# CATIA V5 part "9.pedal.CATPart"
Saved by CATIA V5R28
Part number: 9.pedal
Bounding box of the stored display mesh (mm): x -60 to 51, y -42 to 42, z -15 to 15
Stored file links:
  D:\Catia Cycle design\9.pedal.CATPart
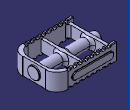
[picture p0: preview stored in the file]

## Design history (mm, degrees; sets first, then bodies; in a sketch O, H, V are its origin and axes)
Set1
  Sketch1 on xy-plane, origin (0, 0, 0), H (1, 0, 0), V (0, 1, 0)
    line L1 (50, 40) -> (50, -40)
    line L2 (50, -40) -> (-50, -40)
    line L3 (-50, -40) -> (-50, 40)
    line L4 (-50, 40) -> (50, 40)
    point P2 (50, -40)
    distance P2 L4 = 80
    length L4 = 100
    vertical: L1 V, L3 V
    horizontal: L2 H, L4 H
    equidistance: L1 L3 O, L2 L4 O
Body1 (main body)
  Pad1: profile Sketch1, direction (0, 0, 1), length 15, mirrored extent
  Sketch2 on end face of Pad1, origin (0, 0, 15), H (1, 0, 0), V (0, 1, 0)
    point P1 (-45, 35)
    line L1 (-45, 35) -> (-2.35, 35)
    line L2 (-2.35, 35) -> (-2.35, 12)
    line L3 (-2.35, 12) -> (-45, 12)
    line L4 (-45, 12) -> (-45, 35)
    point P2 (-2.35, 35)
    point P3 (-2.35, 12)
    point P4 (-45, 12)
    reference projected line E1 (50, 40) -> (-50, 40) from edge [face of Pad1 from Sketch1.L4 | end face of Pad1]
    reference projected line E2 (-50, 40) -> (-50, -40) from edge [face of Pad1 from Sketch1.L3 | end face of Pad1]
    point P5 (2.35, 12)
    point P6 (2.35, 35)
    line L5 (2.35, 35) -> (2.35, 12)
    point P7 (45, 12)
    line L6 (2.35, 12) -> (45, 12)
    point P8 (45, 35)
    line L7 (45, 12) -> (45, 35)
    line L8 (45, 35) -> (2.35, 35)
    point P9 (-45, -35)
    point P10 (-2.35, -35)
    point P11 (-2.35, -12)
    point P12 (-45, -12)
    point P13 (2.35, -12)
    point P14 (2.35, -35)
    point P15 (45, -12)
    point P16 (45, -35)
    line L9 (-45, -35) -> (-2.35, -35)
    line L10 (-2.35, -35) -> (-2.35, -12)
    line L11 (-2.35, -12) -> (-45, -12)
    line L12 (-45, -12) -> (-45, -35)
    line L13 (2.35, -35) -> (2.35, -12)
    line L14 (2.35, -12) -> (45, -12)
    line L15 (45, -12) -> (45, -35)
    line L16 (45, -35) -> (2.35, -35)
    length L1 = 42.65
    length L4 = 23
    distance L1 E1 = 5
    distance L4 E2 = 5
    horizontal: L1 H, L3 H
    vertical: L2 V, L4 V
    symmetry: P3 P5 V, P2 P6 V, L2 L5 V, P4 P7 V, L3 L6 V, P1 P8 V, L4 L7 V, L1 L8 V, P1 P9 H, P2 P10 H, P3 P11 H, P4 P12 H, P5 P13 H, P6 P14 H, P7 P15 H, P8 P16 H, L1 L9 H, L2 L10 H, L3 L11 H, L4 L12 H, L5 L13 H, L6 L14 H, L7 L15 H, L8 L16 H
  Pocket1: profile Sketch2, direction (0, 0, -1), through (limit type 6)
  Sketch3 on face of Pad1 from Sketch1.L1, origin (50, 0, 0), H (0, 1, 0), V (0, 0, 1)
    circle A1 centre (0, 0) radius 7.5
    radius A1 = 7.5
  Pocket2: profile Sketch3, direction (-1, 0, 0), through (limit type 6)
  Sketch4 on face of Pocket1 from Sketch2.L12, origin (-45, 0, 0), H (0, 1, 0), V (0, 0, 1)
    circle A1 centre (0, 0) radius 8.5
    circle A2 centre (0, 0) radius 20
    radius A1 = 8.5
    radius A2 = 20
  Pocket3: profile Sketch4, direction (1, 0, 0), length 42.65
  Sketch5 on face of Pocket1 from Sketch2.L13, origin (2.35, 0, 0), H (0, 1, 0), V (0, 0, 1)
    projected circle E1 centre (0, 0) radius 8.5 from Sketch4.A1
    projected circle E2 centre (0, 0) radius 20 from Sketch4.A2
  Pocket4: profile Sketch5, direction (1, 0, 0), length 42.65
  Fillet1: radius 20, on edge [face of Pocket1 from Sketch2.L8 | face of Pocket4]; edge [face of Pocket4 | face of Pocket1 from Sketch2.L16]; edge [face of Pad1 from Sketch1.L1 | face of Pad1 from Sketch1.L2]; edge [face of Pad1 from Sketch1.L4 | face of Pad1 from Sketch1.L1]
  Sketch6 on end face of Pad1, origin (0, 0, 15), H (1, 0, 0), V (0, 1, 0)
    line L1 (-50, 35) -> (-45, 35)
    line L2 (-45, 35) -> (-45, -35)
    line L3 (-45, -35) -> (-50, -35)
    line L4 (-50, -35) -> (-50, 35)
    reference projected line E1 (-2.35, 35) -> (-45, 35) from edge [end face of Pad1 | face of Pocket1 from Sketch2.L1]
    reference projected line E2 (-45, 35) -> (-45, -35) from edge [end face of Pad1 | face of Pocket3]
    reference projected line E3 (-45, -35) -> (-2.35, -35) from edge [end face of Pad1 | face of Pocket1 from Sketch2.L9]
    reference projected line E4 (-50, 40) -> (-50, -40) from edge [face of Pad1 from Sketch1.L3 | end face of Pad1]
    line L5 (-2.35, 35) -> (2.35, 35)
    line L6 (2.35, 35) -> (2.35, -35)
    line L7 (2.35, -35) -> (-2.35, -35)
    line L8 (-2.35, -35) -> (-2.35, 35)
    reference projected line E5 (-45, -35) -> (-2.35, -35) from edge [end face of Pad1 | face of Pocket1 from Sketch2.L9]
    reference projected line E6 (45, 35) -> (2.35, 35) from edge [end face of Pad1 | face of Pocket1 from Sketch2.L8]
    reference projected line E7 (2.35, 35) -> (2.35, -35) from edge [end face of Pad1 | face of Pocket4]
    reference projected line E8 (-2.35, -35) -> (-2.35, 35) from edge [end face of Pad1 | face of Pocket3]
    horizontal: L1 H, L3 H, L5 H, L7 H
    vertical: L2 V, L4 V, L6 V, L8 V
    coincidence: L1 E1, L2 E2, L3 E3, E4 L4, L7 E5, L5 E6, L6 E7, L8 E8
  Pocket5: profile Sketch6, direction (0, 0, -1), length 5
  Mirror1: of Pocket5, about xy-plane
  Sketch7 on face of Pad1 from Sketch1.L3, origin (-50, 0, 0), H (0, -1, 0), V (0, 0, 1)
    point P1 (-40, 15)
    line L1 (-40, 15) -> (-35, 15)
    line L2 (-35, 15) -> (-35, -15)
    line L3 (-35, -15) -> (-40, -15)
    line L4 (-40, -15) -> (-40, 15)
    point P2 (-35, 15)
    point P3 (-35, -15)
    point P4 (-40, -15)
    reference projected line E1 (-40, -15) -> (40, -15) from edge [start face of Pad1 | face of Pad1 from Sketch1.L3]
    reference projected line E2 (-35, 15) -> (-35, 10) from edge [face of Pad1 from Sketch1.L3 | face of Pocket5]
    reference projected line E3 (-40, -15) -> (-40, 15) from edge [face of Pad1 from Sketch1.L3 | face of Pad1 from Sketch1.L4]
    reference projected line E4 (-40, 15) -> (40, 15) from edge [face of Pad1 from Sketch1.L3 | end face of Pad1]
    point P5 (40, 15)
    point P6 (35, 15)
    point P7 (35, -15)
    point P8 (40, -15)
    line L5 (40, 15) -> (35, 15)
    line L6 (35, 15) -> (35, -15)
    line L7 (35, -15) -> (40, -15)
    line L8 (40, -15) -> (40, 15)
    horizontal: L1 H, L3 H
    vertical: L2 V, L4 V
    coincidence: L3 E1, L2 E2, L4 E3, L1 E4
    symmetry: P1 P5 V, P2 P6 V, P3 P7 V, P4 P8 V, L1 L5 V, L2 L6 V, L3 L7 V, L4 L8 V
  Pad2: profile Sketch7, direction (-1, 0, 0), length 5
  Sketch8 on face of Pad1 from Sketch1.L3, origin (-50, 0, 0), H (0, -1, 0), V (0, 0, 1)
    circle A1 centre (0, 0) radius 7.5
    circle A2 centre (0, 0) radius 8.5
    radius A2 = 8.5
    radius A1 = 7.5
  Pad3: profile Sketch8, direction (-1, 0, 0), length 10
  Sketch9 on face of Pad2, origin (0, 0, 15), H (1, 0, 0), V (0, 1, 0)
    line L1 (-45, 45.6451) -> (-40, 45.6451)
    line L2 (-40, 45.6451) -> (-40, -46.6417)
    line L3 (-40, -46.6417) -> (-45, -46.6417)
    line L4 (-45, -46.6417) -> (-45, 45.6451)
    reference projected line E1 (-45, -35) -> (-45, 35) from edge [face of Pocket3 | end face of Pocket5]
    distance L4 L2 = 5
    horizontal: L1 H, L3 H
    vertical: L2 V, L4 V
    coincidence: L4 E1
  Pocket6: profile Sketch9, direction (0, 0, -1), length 3
  RectPattern1: of Pocket6, direction 1 instances 8, spacing 10, along face of Pad2
  Mirror2: of RectPattern1, about xy-plane
  Fillet2: radius 5, on edge [face of Pocket3 | face of Pocket3 from Sketch4.A1]; edge [face of Pocket3 | face of Pad2]; edge [face of Pocket4 | face of Pocket4 from Sketch5.E1]; edge [face of Pocket3 from Sketch4.A1 | face of Pocket3]; edge [face of Pad2 | face of Pocket3]; edge [face of Pocket4 from Sketch5.E1 | face of Pocket4]
  Sketch10 on face of Pad1 from Sketch1.L1, origin (50, 0, 0), H (0, 1, 0), V (0, 0, 1)
  Pocket7: profile Sketch10, direction (-1, 0, 0), length 1
  Sketch11 on face of Pad2, origin (0, 40, 0), H (-1, 0, 0), V (0, 0, 1)
    construction line L1 (-17.41, 0) -> (42.59, 0)
    point P1 (-17.41, 0)
    line L2 (-17.41, 6.5) -> (42.59, 6.5)
    line L3 (42.59, -6.5) -> (-17.41, -6.5)
    arc A1 centre (42.59, 0) radius 6.5 from (42.59, 6.5) to (42.59, -6.5) cw
    arc A2 centre (-17.41, 0) radius 6.5 from (-17.41, -6.5) to (-17.41, 6.5) cw
    axis line L4 (12.59, 25.9127) -> (12.59, -42.2263)
    distance L1 L2 = 6.5
    length L1 = 60
    distance L4 V = 12.59
    coincidence: P1 H
    horizontal: L1 H
    tangency: A1 L2, A2 L2, A1 L3, A2 L3
    vertical: L4 V
    symmetry: A2 A1 L4
  Pad4: profile Sketch11, direction (0, 1, 0), length 2
  Mirror3: of Pad4, about zx-plane
  Sketch12 on end face of Pocket7, origin (49, 0, 0), H (0, 1, 0), V (0, 0, 1)
    circle A1 centre (0, 0) radius 10
    radius A1 = 10
  Pad5: profile Sketch12, direction (1, 0, 0), length 2
  Fillet3: radius 1, on face of Pad2 (x32); edge [face of Pad2 | face of RectPattern1] (x3); edge [end face of Pocket7 | face of Pad5 from Sketch12.A1]; edge [face of Pad2 | face of Pad2]; end face of Pad4; edge [face of Mirror3 | face of Mirror3]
